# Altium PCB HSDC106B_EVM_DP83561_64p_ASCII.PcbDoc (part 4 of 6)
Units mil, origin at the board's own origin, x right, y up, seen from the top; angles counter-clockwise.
Board outline 8750.24 x 6394.7 mil, 6 copper layers (Top Layer, GND, SIG1, SIG2, GND1, Bottom Layer), stack 60.4 mil thick; 475 components, 330 nets, 1628 pads, 1086 vias.
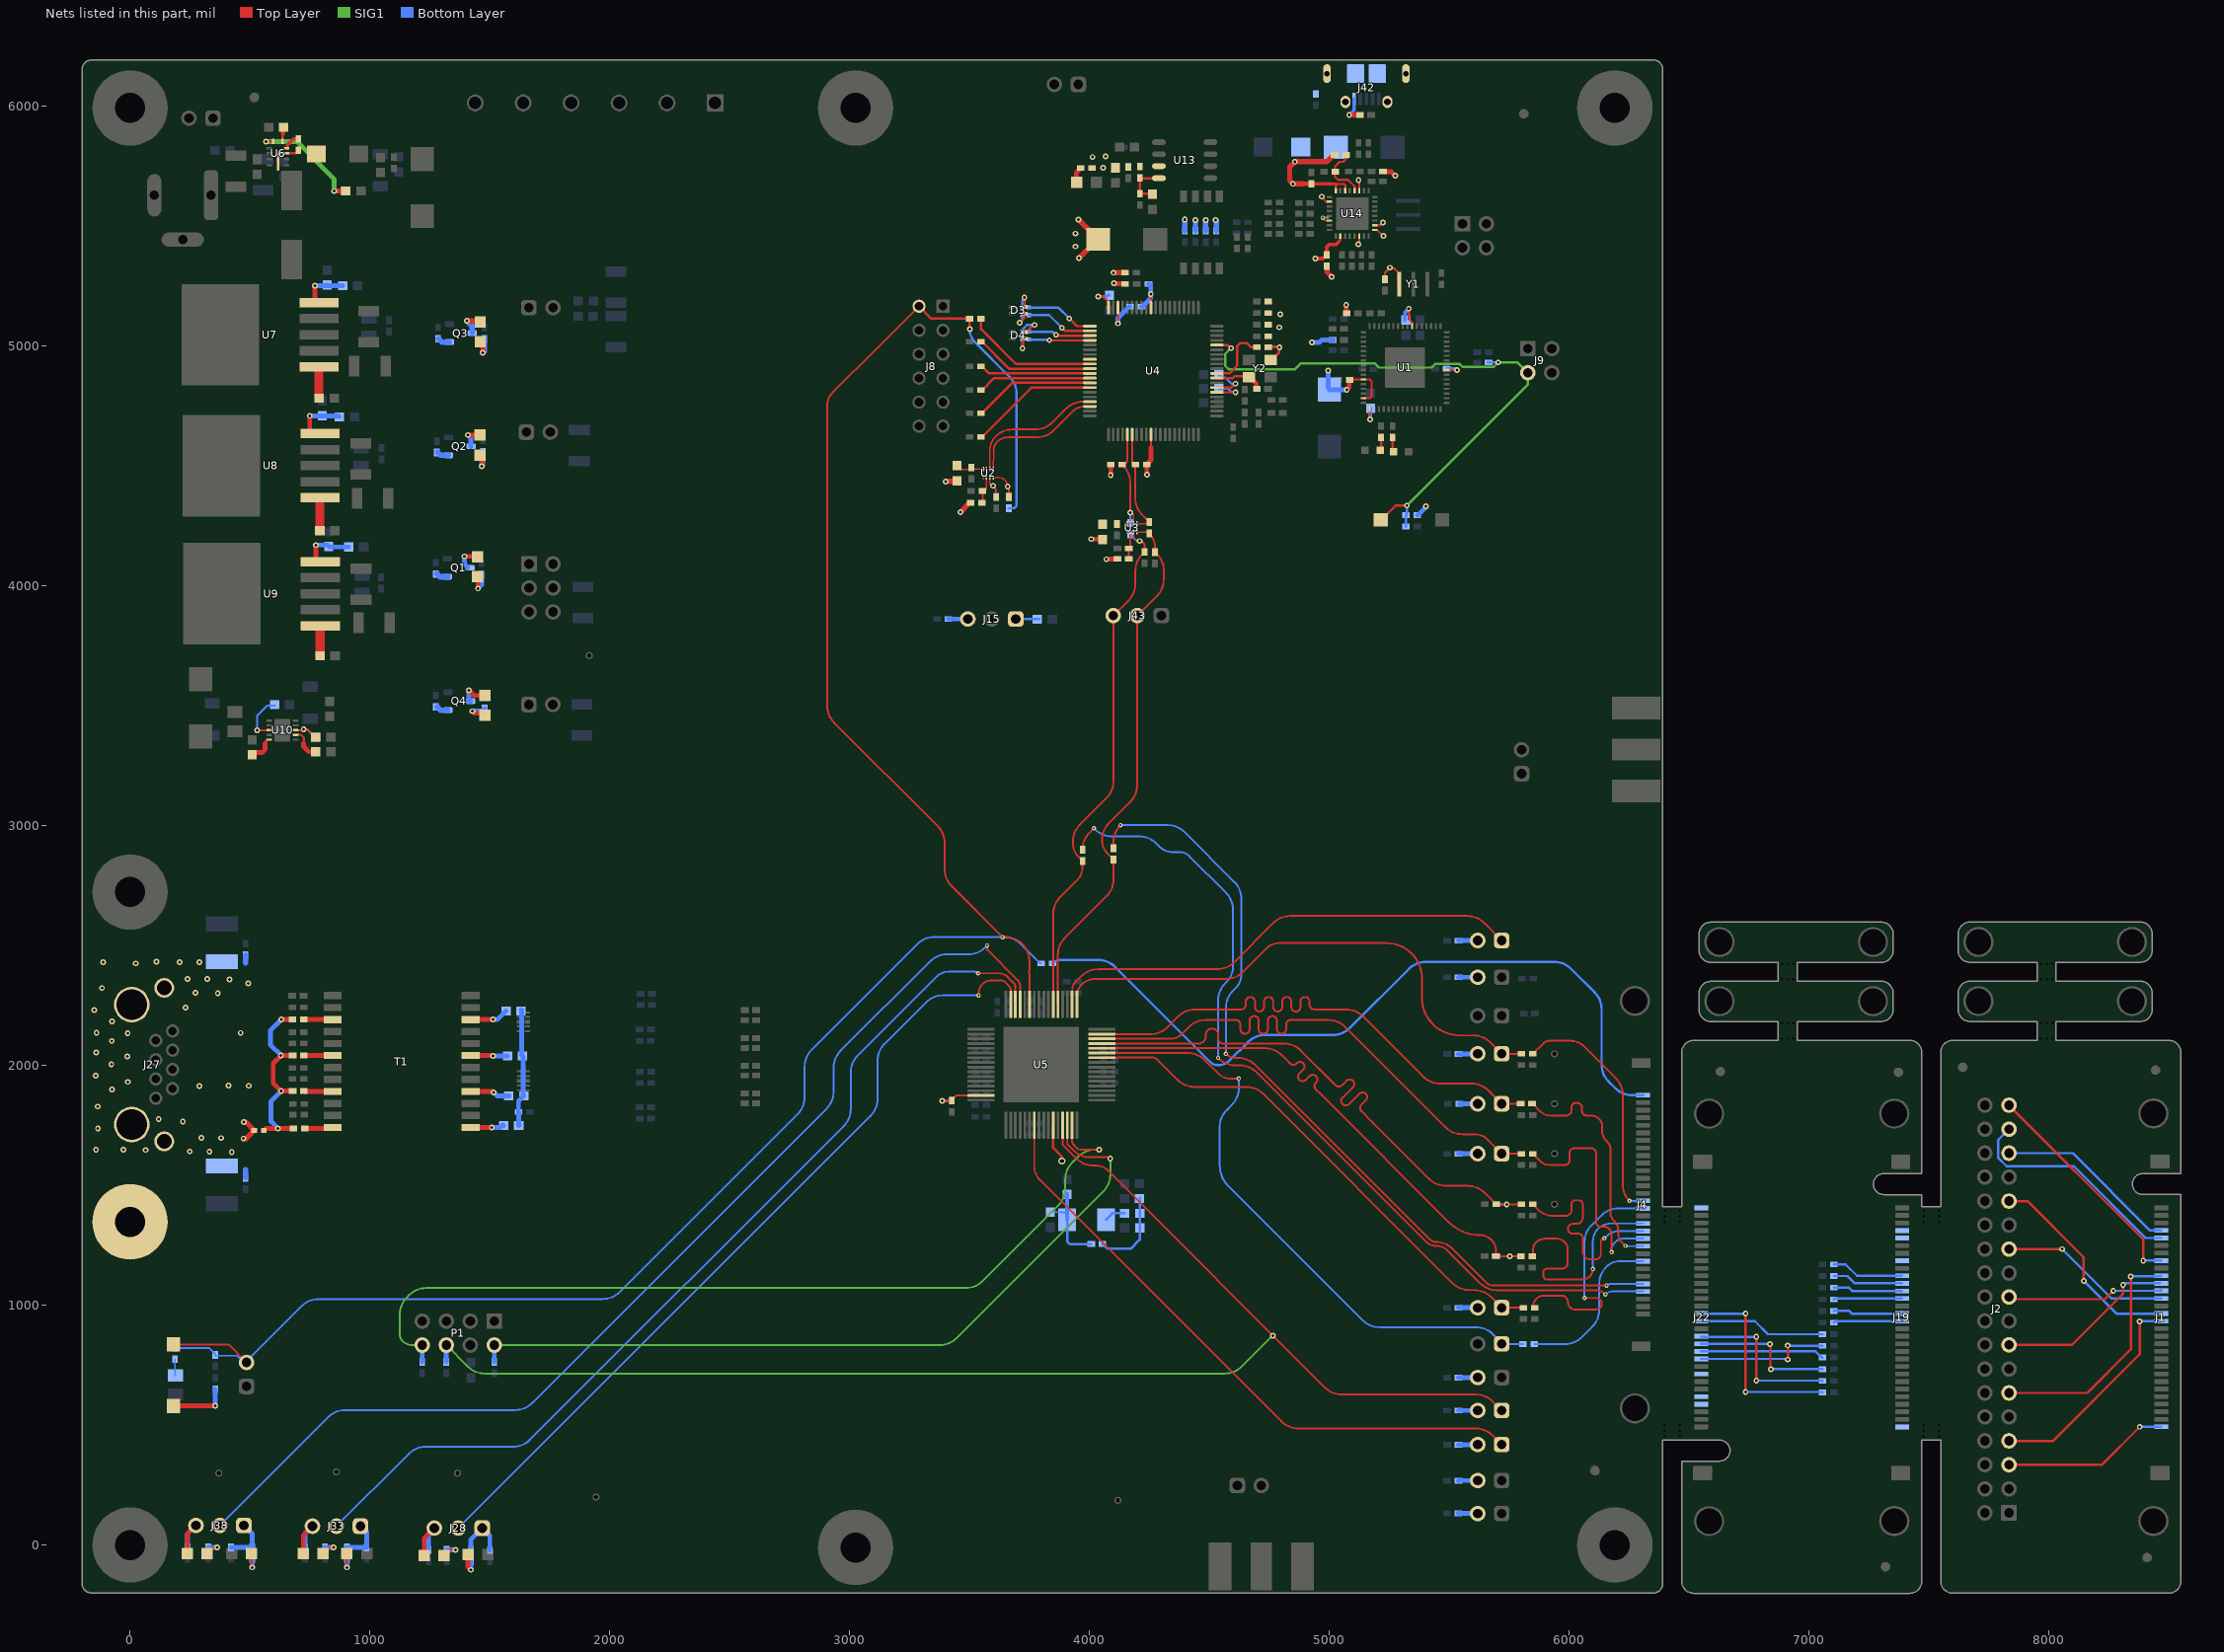
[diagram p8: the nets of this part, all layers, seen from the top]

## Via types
v1: diameter 24, hole 12, Top Layer to Bottom Layer, tented both sides, 905 vias
v2: diameter 24, hole 12, Top Layer to Bottom Layer, 63 vias
v3: diameter 18, hole 7.87, Top Layer to Bottom Layer, tented both sides, 53 vias
v4: diameter 22, hole 10, Top Layer to Bottom Layer, tented both sides, 43 vias
v5: diameter 19.68, hole 7.87, Top Layer to Bottom Layer, 21 vias
v6: diameter 22, hole 12, Top Layer to Bottom Layer, tented both sides, 1 vias

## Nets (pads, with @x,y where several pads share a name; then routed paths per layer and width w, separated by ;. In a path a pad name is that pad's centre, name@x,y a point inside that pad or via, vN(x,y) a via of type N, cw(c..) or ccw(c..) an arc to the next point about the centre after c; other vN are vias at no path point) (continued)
JTAG_TDI: P1.8 R89.2 U5.31 | length 3738.9
  Top Layer w8: U5.31@3927.51,1751.38 3927.51,1685.33 ccw(c3949.83,1685.33) 3934.03,1669.57 3946.87,1656.73 ccw(c3965.96,1675.83) 3965.96,1648.82 v1(4041,1648.82)
  SIG1 w8: P1.8@1218.49,834.31 1178.57,834.31 cw(c1178.57,897.01) 1134.24,852.67 cw(c1157.84,876.27) 1124.47,876.27 1124.47,962.07 cw(c1224.47,962.07) 1153.76,1032.78 1163.6,1042.63 cw(c1234.31,971.92) 1234.31,1071.92 3483.79,1071.92 ccw(c3483.79,1171.92) 3554.5,1101.21 3870.12,1416.82 ccw(c3799.41,1487.53) 3899.41,1487.53 3899.41,1524.82 cw(c3999.41,1524.82) 3928.7,1595.53 3952.7,1619.53 cw(c4023.41,1548.82) 4023.41,1648.82 v1(4041,1648.82)
  Bottom Layer w20: R89.2@1218.49,764.31 P1.8@1218.49,834.31
JTAG_TDO: J34.1 P1.6 R88.2 U5.29 | length 5977
  Top Layer w8: U5.29@3888.14,1751.38 3888.14,1670.56 3947,1611.7 ccw(c4017.71,1682.41) 4017.71,1582.41 4029.6,1582.41 cw(c4029.6,1516.81) 4075.98,1563.2 4982.18,657 ccw(c5052.89,727.71) 5052.89,627.71 5611.43,627.71 cw(c5611.43,527.71) 5682.14,598.42 J34.1@5718.99,561.57
  SIG1 w8: P1.6@1318.49,834.31 1407.9,744.9 ccw(c1478.61,815.61) 1478.61,715.61 4563.94,715.61 ccw(c4563.94,815.61) 4634.65,744.9 4762.57,872.82 v1(4764.47,872.82)
  Bottom Layer w20: R88.2@1318.49,764.31 P1.6@1318.49,834.31
JTAG_TMS: P1.2 R86.2 U5.30 | length 3293.7
  Top Layer w8: U5.30@3907.83,1751.38 3907.83,1673.32 3939.58,1641.57 ccw(c3996.04,1698.04) 3996.04,1618.19 4072.9,1618.19 cw(c4072.9,1598.25) v1(4087,1612.35)
  SIG1 w8: P1.2@1518.49,834.31 3375.72,834.31 ccw(c3375.72,934.31) 3446.43,863.6 4057.71,1474.89 ccw(c3987,1545.6) 4087,1545.6 v1(4087,1612.35)
  Bottom Layer w20: R86.2@1518.49,764.31 P1.2@1518.49,834.31
LED0: J28.2 U5.63 | length 3472
  Top Layer w8: v3(3538,2292.68) 3538,2301.1 cw(c3592.6,2301.1) 3592.6,2355.7 3627.6,2355.7 cw(c3627.6,2325.76) 3648.77,2346.93 3666.31,2329.39 cw(c3653.53,2316.61) 3671.61,2316.61 U5.63@3671.61,2255.08
  Bottom Layer w8: J28.2@1368.5,70.98 3086.87,1789.35 ccw(c3016.16,1860.06) 3116.16,1860.06 3116.16,2019.43 cw(c3216.16,2019.43) 3145.45,2090.15 3318.62,2263.32 cw(c3389.33,2192.61) 3389.33,2292.61 3504.5,2292.61 3504.6,2292.71 v3(3538,2292.68)
LED1: J33.2 U5.62 | length 4006.6
  Top Layer w8: v3(3535.6,2384.61) 3620.76,2384.61 cw(c3620.76,2329.98) 3659.37,2368.63 ; 3659.39,2368.61 3683.45,2344.54 cw(c3664.51,2325.61) 3691.29,2325.61 U5.62@3691.29,2255.08
  Bottom Layer w8: J33.2@860.5,78.98 1162.05,380.53 cw(c1232.76,309.82) 1232.76,409.82 1596.58,409.82 ccw(c1596.58,509.82) 1667.29,439.11 2975.31,1747.13 ccw(c2904.6,1817.84) 3004.6,1817.84 3004.6,1971.13 cw(c3104.6,1971.13) 3033.89,2041.84 3329.6,2337.55 3363.13,2371.08 cw(c3412.38,2321.82) 3412.38,2391.48 3519,2391.48 cw(c3519,2368.01) v3(3535.6,2384.61)
LED2: J38.2 U5.61 | length 4582.9
  Top Layer w8: v3(3573.6,2500.61) 3573.6,2483.1 3700.6,2356.1 cw(c3675.54,2331.05) 3710.98,2331.05 U5.61@3710.98,2255.08
  Bottom Layer w8: J38.2@374.5,81.98 826.54,534.03 cw(c897.26,463.32) 897.26,563.32 1605.83,563.32 ccw(c1605.83,663.32) 1676.54,592.6 2903.59,1819.65 ccw(c2832.88,1890.36) 2932.88,1890.36 2932.88,1989.99 cw(c3032.88,1989.99) 2962.17,2060.7 3335.79,2434.32 cw(c3406.5,2363.61) 3406.5,2463.61 3495.18,2463.61 ccw(c3495.18,2563.61) 3565.89,2492.9 v3(3573.6,2500.61)
MCU_VCC: C10.1 C11.1 C12.1 C21.1 C22.1 C23.1 C112.1 C113.1 C114.1 C129.1 R4.2 R8.2 R36.2 R38.2 R40.2 R41.2 R49.2 R50.2 R52.2 R53.2 R62.2 R63.2 R64.2 R65.2 R66.2 R67.2 R75.1 R76.1 R174.2 R175.2 R178.2 R179.2 R198.2 U1.11 U1.15 U1.40 U4.18 U4.50 U13.3 U14.3 U14.6 U14.8 U14.25 U14.26 | length 2588.9
  Top Layer w9: 5008.25,5676.98 5018.82,5676.98 ; U14.6@5065.88,5647.99 5066.3,5648.41 5066.3,5671.46 5061.03,5676.73 5035.78,5676.73 ; C11.1@5091.15,4861.48 5168.22,4861.48 5176,4853.7 5176,4789.7 5169.04,4782.74 U1.15@5142.77,4782.74 ; U14.3@5124.94,5647.99 v1@5124.94,5690.64 ; U14.25@5189.32,5484.41 5199.52,5484.41 5224.41,5459.52 v1(5226.43,5459.52) ; U14.26@5189.9,5504.29 5212.89,5504.29 v1(5223.77,5515.18) ; U1.40@5489.22,4900.85 v1(5532.85,4900.85) ; 5018.82,5676.98 5029.39,5676.98 5029.64,5676.73 5035.78,5676.73 ; 5018.82,5676.98 5026.51,5669.29 U14.8@5026.51,5647.99 5026.93,5648.41 5026.93,5668.3 5027.14,5668.1 5035.78,5676.73
  Top Layer w10: v1(4118.83,5094.61) U4.18@4118.83,5161.23 ; 4256.63,4577.61 U4.50@4256.63,4631.7
  Top Layer w15: C129.1@4925.63,5676.98 5008.25,5676.98
  Top Layer w20: v1(4007.6,4195.61) 4054.1,4195.61 R41.2@4055.6,4194.11 ; v1(4070.38,4111.55) 4101.5,4111.55 4101.75,4111.8 4115.17,4111.8 R38.2@4116.98,4113.61 ; v1(4088.6,4462.61) R66.2@4088.6,4506.61 ; v1(4239.6,4463.61) 4239.1,4464.11 4239.1,4506.61 4242.54,4506.61 4244.35,4508.42 4244.35,4511.85 4256.63,4524.14 4256.63,4577.61 ; 4891.01,5676.98 C129.1@4925.63,5676.98 ; R179.2@4989,5334.08 4990.81,5332.27 4990.81,5308.3 v1(5009.12,5289.99) ; R8.2@5070.41,5138.14 v1(5070.41,5172.52) ; v1(5072.8,4817.7) 5072.8,4818.78 5083.11,4829.08 5083.11,4858.58 C11.1@5084.22,4859.7 ; R178.2@5223.62,5729 5225.43,5727.19 5258.15,5727.19 5273.72,5711.62 5273.72,5711.18 v1(5275.24,5711.18)
  Top Layer w22: v1(3400.32,4435.84) 3400.7,4436.22 3445.71,4436.22 R40.2@3448.6,4439.11 ; v1(3461.6,4307.61) 3461.98,4307.99 3461.98,4308.55 3500.04,4346.61 R36.2@3503.98,4346.61 ; v1(3953.6,5527.76) 3954.35,5527.76 3997.31,5484.8 3997.31,5482.83 C21.1@4034.54,5445.61 ; v1(3956.6,5367.67) C21.1@4034.54,5445.61 ; C21.1@4036.5,5445.61 C21.1@4034.54,5445.61 ; v1(4100.6,5306.61) C22.1@4148.17,5306.61 ; v1(4102.3,5262.61) 4102.84,5262.61 4105.03,5260.42 4147.35,5260.42 C23.1@4148.17,5259.61 ; 4891.01,5676.98 v1(4848.25,5676.98) 4834.63,5690.61 4834.63,5747.61 v1(4856.63,5769.61) 4989.63,5769.61 5017.63,5797.61 R198.2@5022.63,5797.61
  Bottom Layer w15: C12.1@5489.62,4905.7 5528,4905.7 v1(5532.85,4900.85)
  Bottom Layer w20: v1(4118.83,5094.61) 4118.83,5118.28 4165.29,5164.73 R76.1@4169.23,5164.73 ; v1(4927,5015.7) 4958,5015.7 4968,5025.7 R4.2@5019,5025.7 ; v1(4995.6,4898.08) 4995.6,4831.77 ccw(c5012.67,4831.77) C10.1@5000.6,4819.7 ; C10.1@5000,4820.79 5003.09,4817.7 v1(5072.8,4817.7) ; R75.1@5366.62,4295.61 5370.56,4295.61 5402.25,4327.3 5402.25,4331.23 v1(5403.02,4332)
  Bottom Layer w22: R62.2@4397.6,5482.23 v1(4397.6,5528.61) ; R63.2@4441.6,5482.23 v1(4441.6,5526.61) ; R64.2@4484.6,5482.23 v1(4484.6,5526.61) ; v1(4525.6,5526.61) 4528.6,5523.61 R65.2@4528.6,5482.23 ; v1(4484.6,5526.61) ccw(c4483.6,5526.61) 4483.6,5527.61 v1(4484.6,5526.61)
  other v1: 4791.66,5078.25 4795.6,5133.5 3941.6,5415.61 3941.6,5469.61 5122,5692.7 4057.6,5744.1 4012.6,5788.61 4066.6,5791.61
MDC: J43.3 R11.1 R48.1 R54.1 U3.3 U5.54 | length 2210.2
  Top Layer w6: U3.3@4183.49,4224.89 4183.49,4213.72 ccw(c4209.6,4213.72) v1(4209.6,4187.61)
  Top Layer w8: U5.54@3848.77,2255.08 3848.77,2632.36 cw(c3948.77,2632.36) 3878.06,2703.07 3949.53,2774.54 ccw(c3896.75,2827.31) 3971.39,2827.31 R11.1@3971.39,2852.9 3954.58,2869.71 cw(c4012.47,2927.61) 3930.6,2927.61 3930.6,2933.18 cw(c4030.6,2933.18) 3959.89,3003.9 4070.31,3114.32 ccw(c3999.6,3185.03) 4099.6,3185.03 J43.3@4099.6,3876.61 4162.31,3939.32 ccw(c4091.6,4010.03) 4191.6,4010.03 4191.6,4064.61 cw(c4284.84,4064.61) 4218.91,4130.54 R48.1@4230.1,4141.73 4230.1,4167.11 ccw(c4209.6,4167.11) v1(4209.6,4187.61)
  Bottom Layer w8: R54.1@4169.71,4215.05 4188.35,4196.41 ccw(c4209.6,4217.66) v1(4209.6,4187.61)
MDC_1: J1.8 J2.31 | length 769.1
  Bottom Layer w10: J2.31@7833.6,1634.61 8099.99,1634.61 8422.39,1312.2 J1.8@8469.11,1312.2
MDC_2: J22.8
MDC_CS: J4.8 R11.2 | length 3629.3
  Top Layer w8: R11.2@3971.39,2900.15 3971.39,2900.97 cw(c4071.39,2900.97) 4000.68,2971.69 v3(4018.6,2989.61) ; v3(4536.62,2031.61) 4537.8,2030.42 ccw(c4608.51,2101.13) 4540.24,2028.07 ccw(c4608.51,2101.13) 4608.51,2001.13 4626.65,2001.13 cw(c4626.65,1901.13) 4697.36,1971.84 5404.34,1264.86 ccw(c5446,1306.52) 5446,1247.61 cw(c5446,1180.98) 5493.11,1228.09 5628.93,1092.27 ccw(c5699.64,1162.98) 5699.64,1062.98 6109.64,1062.98 cw(c6109.64,1003.65) v3(6151.6,1045.61)
  Bottom Layer w8: v3(4018.6,2989.61) 4022.78,2985.43 ccw(c4093.49,3056.14) 4093.49,2956.14 4206.64,2956.14 cw(c4206.64,2856.14) 4277.35,2926.85 4289.6,2914.61 ccw(c4349.95,2974.96) 4349.95,2889.61 4377.32,2889.61 cw(c4377.32,2833.4) 4417.06,2873.14 4568.6,2721.61 cw(c4497.89,2650.9) 4597.89,2650.9 4597.89,2410.8 cw(c4511.35,2410.8) 4572.54,2349.61 4565.91,2342.97 ccw(c4636.62,2272.26) 4536.62,2272.26 v3(4536.62,2031.61) ; v3(6151.6,1045.61) cw(c6181.03,1016.18) 6181.03,1057.8 J4.8@6308.86,1057.8
MDC_LP: J19.8
MDC_MSP: R54.2 R66.1 U3.6 U4.45 | length 445
  Top Layer w6: v1(4169.71,4305.61) cw(c4169.71,4291.83) 4183.49,4291.83 U3.6@4183.49,4260.32
  Top Layer w8: U4.45@4158.2,4631.7 4158.2,4528.97 cw(c4135.84,4528.97) R66.1@4135.84,4506.61 4140.42,4502.03 cw(c4069.71,4431.32) 4169.71,4431.32 v1(4169.71,4305.61)
  Bottom Layer w8: R54.2@4169.71,4262.29 v1(4169.71,4305.61)
MDIO: J43.2 R12.1 R56.1 R85.2 U3.4 U5.53 | length 2234.9
  Top Layer w6: U3.4@4197.27,4224.89 4244.07,4224.89 cw(c4244.07,4219.36) R56.1@4249.6,4219.36
  Top Layer w8: U5.53@3868.46,2255.08 3868.46,2461.73 cw(c3968.46,2461.73) 3897.75,2532.45 4071.22,2705.92 ccw(c4000.51,2776.63) 4100.51,2776.63 R12.1@4100.51,2858.98 4075.02,2884.47 cw(c4129.16,2938.61) 4052.6,2938.61 4052.6,2941.18 cw(c4152.6,2941.18) 4081.89,3011.9 4170.31,3100.32 ccw(c4099.6,3171.03) 4199.6,3171.03 J43.2@4199.6,3876.61 4280.31,3957.32 ccw(c4209.6,4028.03) 4309.6,4028.03 4309.6,4067.61 ccw(c4219.98,4067.61) 4283.35,4130.98 R85.2@4273.1,4141.23 4273.1,4162.63 ccw(c4192.86,4162.63) R56.1@4249.62,4219.34
MDIO_1: J1.10 J2.33 | length 957.2
  Bottom Layer w10: J2.33@7833.6,1734.61 7788.24,1689.25 7788.24,1615.82 7824.1,1579.96 7833.27,1579.96 7833.42,1579.96 cw(c7833.6,1534.61) 7833.78,1579.96 7833.93,1579.96 8104.04,1579.96 8403.29,1280.71 J1.10@8469.11,1280.71
MDIO_2: J22.10
MDIO_CS: J4.10 R12.2 | length 3550.9
  Top Layer w8: R12.2@4100.51,2900.15 4100.51,2932.48 cw(c4199.68,2932.48) v3(4129.55,3002.61) ; v3(4568.6,2048.94) ccw(c4611.33,2091.67) 4611.33,2031.24 4628.75,2031.24 cw(c4620.18,1931.61) 4690.89,2002.32 5417.48,1275.73 ccw(c5444.6,1302.84) 5444.6,1264.49 cw(c5444.6,1167.2) 5513.4,1236 5656.6,1092.79 ccw(c5682.02,1118.22) 5682.02,1082.26 v3(6156.02,1082.26)
  Bottom Layer w8: v3(4129.55,3002.61) 4326.04,3002.61 cw(c4326.04,2902.61) 4396.75,2973.32 4604.31,2765.76 cw(c4533.6,2695.05) 4633.6,2695.05 4633.6,2380.48 cw(c4551.66,2380.48) 4609.6,2322.54 4597.89,2310.83 ccw(c4668.6,2240.12) 4568.6,2240.12 v3(4568.6,2048.94) ; v3(6156.02,1082.26) cw(c6172.99,1065.29) 6172.99,1089.29 J4.10@6308.86,1089.29
MDIO_LP: J19.10
MDIO_MSP: R56.2 R67.1 U3.5 U4.46 | length 446.6
  Top Layer w6: U3.5@4197.27,4260.32 4234.43,4260.32 ccw(c4234.43,4281.78) R56.2@4249.6,4266.61
  Top Layer w8: U4.46@4177.89,4631.7 4177.89,4520.07 ccw(c4191.35,4520.07) R67.1@4191.35,4506.61 4191.35,4382.61 4191.35,4366.27 ccw(c4291.35,4366.27) 4191.35,4366.22 ccw(c4291.35,4366.27) 4214.29,4302.54 ccw(c4291.35,4366.27) 4220.64,4295.56 R56.2@4249.6,4266.61
MSP_XIN: C15.1 U4.69 Y2.3 | length 203.6
  Top Layer w10: U4.69@4531.24,4866.94 4597.38,4866.94 4605.93,4875.48 4661.02,4875.48 Y2.3@4665.32,4871.17 Y2.3@4669.26,4871.17 ; C15.1@4696.17,4823.79 C15.1@4697.35,4822.61
  Top Layer w20: Y2.3@4669.26,4871.17 4696.17,4844.26 C15.1@4696.17,4823.79
MSP_XOUT: R68.2 U4.70 | length 272.3
  Top Layer w10: U4.70@4531.24,4886.62 4583.06,4886.62 4615.6,4919.16 4615.6,4999.61 4627.65,5011.66 4657.72,5011.66 4673.78,4995.61 R68.2@4697.98,4995.61
NetC4_1: C4.1 R7.2 Y1.1 | length 207.6
  Top Layer w9: C4.1@5232.1,5279.17 5232.2,5279.27 5232.2,5307.2 v1(5252.6,5327.61) 5254.25,5325.95 5269.01,5325.95 5288.17,5306.79 5288.17,5261.98 Y1.1@5291.54,5258.61
  Bottom Layer w9: R7.2@5232.1,5279.17 5232.1,5307.11 v1(5252.6,5327.61)
NetC6_1: C6.1 U1.55 | length 133.3
  Top Layer w9: v1(5331.6,5156.61) 5331.6,5113.09 5345.52,5099.17 U1.55@5345.52,5083.92
  Bottom Layer w15: C6.1@5315.99,5108.2 5315.99,5141 v1(5331.6,5156.61)
NetC7_1: C7.1 U1.17 | length 91
  Top Layer w9: U1.17@5168.32,4737.47 5168.32,4696.38 v1(5170,4694.7)
  Bottom Layer w15: v1(5170,4694.7) 5171,4694.7 C7.1@5171,4741.2
NetC13_1: C13.1 R40.1 U2.7 U2.8 | length 134.6
  Top Layer w6: R40.1@3448.6,4502.1 3464.25,4486.45 3499.42,4486.45 C13.1@3507.2,4494.23 3513.2,4488.23 U2.8@3557.26,4488.23 U2.7@3571.04,4488.23
NetC14_1: C14.1 R41.1 U3.7 U3.8 | length 13.8
  Top Layer w6: U3.8@4155.93,4260.32 U3.7@4169.71,4260.32
NetC16_1: C16.1 R68.1 Y2.1 | length 160.2
  Top Layer w10: R68.1@4745.22,4995.61 4787.1,4995.61 4789.78,4992.93 4789.78,4972.01 4759.81,4942.04 Y2.1@4755.87,4942.04
  Bottom Layer w10: C16.1@4745.22,4995.61 v1(4792.46,4995.61)
NetC17_1: C17.1 U4.67 | length 170.7
  Top Layer w10: U4.67@4531.24,4827.57 4531.58,4827.91 4592.06,4827.91 4607.84,4843.7 v1(4609.32,4843.7)
  Bottom Layer w10: C17.1@4539.09,4881.61 4551.37,4869.34 4566.42,4869.34 4592.06,4843.7 v1(4609.32,4843.7)
NetC18_1: C18.1 U4.20 | length 128
  Top Layer w10: v1(4036.6,5207.61) 4056.91,5207.61 4078.56,5185.95 4078.56,5185.26 4079.46,5184.36 U4.20@4079.46,5161.23
  Bottom Layer w10: v1(4036.6,5207.61) 4071.6,5207.61 4079.6,5215.61 C18.1@4083.6,5211.61
NetC20_1: C20.1 U4.66 | length 155
  Top Layer w10: U4.66@4531.24,4807.88 v1(4609.32,4807.88)
  Bottom Layer w10: C20.1@4538.76,4823.24 4577.34,4823.24 4591.92,4808.66 4608.54,4808.66 v1(4609.32,4807.88)
NetC24_1: C24.1 R76.2 U4.11 | length 175
  Top Layer w10: v1(4255.83,5216.63) 4256.61,5215.85 U4.11@4256.63,5161.23
  Bottom Layer w20: R76.2@4216.47,5164.73 4220.41,5164.73 4255.83,5200.16 v1(4255.83,5216.63) 4255.83,5253.69 4249.92,5259.61 C24.1@4246.62,5259.61
NetC47_1: C47.1 R80.1 | length 68.2
  Bottom Layer w8: R80.1@187.29,775.18 187.29,709.8 C47.1@189.29,707.8
NetC48_1: C48.1 R77.1 R81.1 XTAL1.2 | length 383
  Bottom Layer w8: C48.1@3835.97,1388.79 3882.12,1388.79 cw(c3882.12,1353.65) XTAL1.2@3906.97,1378.5
  Bottom Layer w10: XTAL1.2@3907.26,1356.8 3907.26,1265.51 3916.97,1255.8 R81.1@4007.35,1255.8
  Bottom Layer w15: XTAL1.2@3903.96,1388.79 XTAL1.2@3906.97,1391.8 ; R77.1@3906.97,1466.31 XTAL1.2@3906.97,1391.8 ; XTAL1.2@3907.26,1356.8 3906.97,1357.09 3906.97,1378.5 XTAL1.2@3906.97,1391.8
NetC49_1: C49.1 R78.1 R81.2 R82.1 | length 353.6
  Bottom Layer w10: R81.2@4054.59,1255.8 4074.59,1235.8 4171.97,1235.8 4209.97,1273.8 C49.1@4209.97,1322.8 R78.1@4209.97,1383.8 4209.97,1447.3 R82.1@4209.47,1447.8
NetC51_2: C51.2 R83.1 U5.15 | length 214.4
  Top Layer w8: v1(3385.57,1853.23) C51.2@3426.41,1853.23 3426.41,1857.17 3444.52,1875.27 U5.15@3547.71,1875.27
  Bottom Layer w8: v1(3385.57,1853.23) R83.1@3426.41,1853.23
NetC54_1: C54.1 C69.1 C72.1 C79.1 R126.2 | length 504.7
  Bottom Layer w20: C54.1@1623.1,1751.61 C54.1@1620.5,1749 1619.94,1749.56 1619.94,1805.44 R126.2@1619.38,1806 1619.38,1851.92 1640.98,1873.53 C69.1@1641.97,1873.53 1639.23,1876.27 1639.23,2037.26 C72.1@1636.5,2040 1633.23,2043.26 C79.1@1633.23,2231.41 ; C79.1@1629.97,2231.68 C79.1@1633.23,2228.41
NetC54_2: C54.2 T1.1 | length 144
  Top Layer w20: T1.1@1419.86,1741.7 T1.1@1419.86,1741.7 1508.05,1741.65 v1(1508.09,1741.61)
  Bottom Layer w20: v1(1508.09,1741.61) 1542.38,1741.61 1553.64,1752.87 C54.2@1557.5,1749
NetC56_1: C56.1 U6.4 | length 73.4
  Top Layer w10: U6.4@652.03,5825.18 655.72,5825.18 655.8,5825.26 655.8,5838.31
  Top Layer w15: 655.8,5838.31 681.68,5864.19 C56.1@701.6,5864.19
NetC56_2: C56.2 L1.1 U6.3 U6.12 | length 125.8
  Top Layer w10: U6.12@616.6,5767.58 616.6,5798.43 623.67,5805.5 U6.3@652.03,5805.5 694.08,5805.5 701.6,5813.01 C56.2@701.6,5816.95
NetC62_1: C62.1 U6.5 | length 61
  Top Layer w10: U6.5@636.28,5853.72 636.28,5886.66
  Top Layer w20: 637.88,5886.66 637.88,5910.89 C62.1@640.6,5913.61
NetC69_2: C69.2 T1.4 | length 166.7
  Top Layer w20: T1.4@1419.86,1891.7 1511.01,1891.7 1514.57,1888.14 v1(1515.65,1888.14)
  Bottom Layer w20: v1(1515.65,1888.14) 1530.31,1873.48 1578.93,1873.48 C69.2@1578.98,1873.53
NetC72_2: C72.2 T1.7 | length 214.2
  Top Layer w20: T1.7@1419.86,2041.7 1510.88,2041.7 1512.58,2040 v1(1513.66,2040) ; T1.7@1424.59,2041.61 1484.43,2041.61
  Bottom Layer w20: v1(1513.66,2040) C72.2@1573.5,2040
NetC79_2: C79.2 T1.10 | length 162.7
  Top Layer w20: T1.10@1419.86,2191.7 v1(1513.87,2191.7)
  Bottom Layer w20: v1(1513.87,2191.7) 1531.2,2191.7 C79.2@1567.5,2228
NetC82_1: C82.1 R107.1 R114.1 R117.1 R123.1 | length 819.7
  Top Layer w20: C82.1@557.28,1729.61 558.94,1729.61 566.94,1737.61 v1(616,1737.61) R107.1@680.98,1737.61 ; v1@628,2191 cw(c630.64,2188.36) v1(630.64,2192.09) R123.1@676.38,2192.09 ; R114.1@677.76,1893.61 v1(629.82,1893.61) 597,1926.43 597,2009.08 629.47,2041.56 v1(629.47,2042.64) R117.1@677.76,2041.7
  Bottom Layer w20: v1(616,1737.61) 616,1738.69 587.95,1766.74 587.95,1851.73 v1(629.82,1893.61) ; v1(629.47,2042.64) 585,2087.12 585,2146.45 v1(630.64,2192.09)
NetC94_1: C94.1 U10.7 | length 135.4
  Top Layer w9: U10.7@690.12,3378.7 U10.7@690.12,3379.01 712.68,3379.01 724,3367.7 724,3342.7
  Top Layer w20: 724,3342.7 724,3330.22 745.62,3308.61 C94.1@774.1,3308.61
NetC115_1: C115.1 R174.1 R176.2 U13.4 | length 199.7
  Top Layer w10: C115.1@4263.6,5633.61 4260.65,5636.56 R176.2@4210,5636.56 R174.1@4210,5701.42 4210.72,5700.7 U13.4@4289.72,5700.7
NetC116_1: C116.1 C117.2 D9.2 J42.1 | length 120.9
  Top Layer w20: v1(5082.98,5963.68) 5083.8,5964.5 5121.67,5964.5 C117.2@5127.42,5964.5
  Bottom Layer w15: v1(5082.98,5963.68) 5103.65,5984.35 5103.65,6029.3 J42.1@5103.65,6031.3
NetC126_1: C126.1 R198.1 U14.4 | length 234.5
  Top Layer w9: R198.1@5069.24,5797.7 5067.18,5795.64 5067.18,5778.65 5057.23,5768.7 5043,5768.7 5024.62,5750.32 C126.1@5024.62,5727.7 5024.62,5705.08 5036,5693.7 5078,5693.7 5105.25,5666.45 U14.4@5105.25,5647.99
NetD1_2: D1.2 R1.1 | length 54.9
  Top Layer w10: D1.2@5211.78,4565.7 ccw(c5201.59,4575.89) 5216,4575.89 R1.1@5216,4619.46
NetD2_2: D2.2 R2.1 | length 60.4
  Top Layer w10: R2.1@5264,4619.46 5264,4568.73 ccw(c5276.29,4568.73) D2.2@5267.6,4560.04
NetD3_1: D3.1 R70.1 | length 85.2
  Top Layer w10: v1(3708.6,5097.61) 3728.72,5117.73 D3.1@3728.72,5136.23
  Bottom Layer w10: v1(3708.6,5097.61) 3721.06,5110.06 R70.1@3721.06,5129.86 R70.1@3720.27,5129.86
NetD3_2: D3.2 R69.1 | length 84.2
  Top Layer w10: D3.2@3728.72,5163.79 v1(3728.72,5202.61)
  Bottom Layer w10: R69.1@3721.86,5162.38 R69.1@3721.06,5161.57 3721.06,5191.15 3728.72,5198.82 v1(3728.72,5202.61)
NetD4_1: D4.1 R72.1 | length 83.5
  Top Layer w10: v1(3720.6,4990.61) 3723.28,4993.28 3723.28,5028.2 3726.15,5031.08 D4.1@3730.17,5031.08
  Bottom Layer w10: v1(3720.6,4990.61) 3720.85,4990.86 3720.85,5026.89 R72.1@3721.11,5027.14
NetD4_2: D4.2 R71.1 | length 120
  Top Layer w10: D4.2@3730.17,5058.64 3736.07,5058.64 3763.36,5085.93 3767.92,5085.93 v1(3770.6,5088.61)
  Bottom Layer w10: R71.1@3721.11,5060.61 3721.9,5060.61 3725.17,5063.87 3725.17,5074.21 3739.57,5088.61 v1(3770.6,5088.61)
NetD5_1: D5.1 R102.1 | length 119.6
  Top Layer w20: D5.1@1448.6,4039.27 1450.6,4037.27 v1(1450.6,3989.61)
  Bottom Layer w20: v1(1450.6,3989.61) 1465.6,4004.61 R102.1@1465.6,4052.47
NetD5_2: D5.2 Q1.3 | length 110.1
  Top Layer w20: v1(1394.6,4123.61) 1448.6,4123.61 D5.2@1450.6,4125.61
  Bottom Layer w20: v1(1394.6,4123.61) 1394.6,4090.47 1407.56,4077.51 Q1.3@1407.56,4075.7
NetD6_1: D6.1 R103.1 | length 109.5
  Top Layer w20: D6.1@1458,4546.36 1466.6,4537.76 v1(1466.6,4499.61)
  Bottom Layer w20: v1@1469.6,4501.61 1471.6,4503.61 R103.1@1471.6,4559.98
NetD6_2: D6.2 Q2.3 | length 102.4
  Top Layer w20: v1@1409,4627.7 1410.34,4629.04 D6.2@1458,4629.04
  Bottom Layer w20: v1@1409,4629.7 1409,4628.55 1421.41,4616.14 1421.41,4583.91 1421.65,4583.68 Q2.3@1421.65,4582.1
  other v1: 1408,4629.7
NetD7_1: D7.1 R104.1 | length 110.4
  Top Layer w23: D7.1@1460,5018.36 1470.6,5007.76 v1(1470.6,4972.61)
  Bottom Layer w23: v1(1470.6,4972.61) 1477.6,4979.61 R104.1@1477.6,5029.98
NetD7_2: D7.2 Q3.3 | length 117.5
  Top Layer w23: v1(1405,5105.7) 1455.34,5105.7 D7.2@1460,5101.04
  Bottom Layer w23: v1@1404.54,5105.7 1404.73,5105.7 1405.19,5105.24 1405.19,5104.51 1425.21,5084.49 1425.21,5055.01 1425.52,5054.7 Q3.3@1426.24,5054.7
NetD8_1: D8.1 R105.1 | length 118.9
  Top Layer w20: v1(1426.4,3477.58) 1427.48,3477.58 1435.89,3469.17 1469.89,3469.17 D8.1@1478.6,3460.46
  Bottom Layer w20: v1(1426.4,3477.58) 1427.17,3478.34 1466.96,3478.34 1472.85,3484.24 1476.79,3484.24 1478.6,3486.05 R105.1@1478.6,3489.98
NetD8_2: D8.2 Q4.3 | length 126.7
  Top Layer w20: v1(1412.6,3564.8) 1434.26,3543.13 D8.2@1478.6,3543.13
  Bottom Layer w20: v1(1412.6,3564.8) 1412.6,3521.51 1414.41,3519.7 Q4.3@1420.24,3519.7
NetJ15_1: J15.1 R90.2 | length 95.6
  Bottom Layer w10: J15.1@3697.83,3867 3702.83,3862 R90.2@3791.33,3862
NetJ15_3: J15.3 R87.1 | length 88.4
  Bottom Layer w20: R87.1@3411.45,3862 J15.3@3492.83,3862 J15.3@3497.83,3867
NetJ28_1: J28.1 R149.2 R150.2 | length 215.6
  Bottom Layer w20: R149.2@1421.5,-19.77 1421.5,23.98 J28.1@1468.5,70.98 1500,39.48 R150.2@1500,-21.38
NetJ28_3: J28.3 LD1.2 R148.1 | length 233
  Top Layer w20: LD1.2@1226.66,-44 1226.66,29.14 J28.3@1268.5,70.98
  Bottom Layer w20: R148.1@1244.5,-19.77 1244.5,46.98 J28.3@1268.5,70.98
NetJ29_2: J29.2 R151.1 | length 80.8
  Bottom Layer w20: R151.1@5538.56,1631.93 5538.56,1632.34 J29.2@5618.99,1632.34
NetJ30_2: J30.2 R153.1 | length 80.8
  Bottom Layer w20: R153.1@5542.27,1840.17 5542.27,1840.58 J30.2@5618.99,1840.58 J30.2@5622.7,1840.58
NetJ31_2: J31.2 R156.1 | length 80.8
  Bottom Layer w20: R156.1@5538.56,2048.41 5538.56,2048.82 J31.2@5618.99,2048.82
NetJ32_2: J32.2 R160.1 | length 80.8
  Bottom Layer w20: R160.1@5538.56,989.59 5538.56,990 J32.2@5618.99,990
NetJ33_1: J33.1 R161.2 R162.2 | length 181.3
  Bottom Layer w20: R161.2@904,-9.77 R162.2@986,-9.77 986,53.48 J33.1@960.5,78.98
NetJ33_3: J33.3 LD3.2 R159.1 | length 231.2
  Top Layer w20: LD3.2@722.56,-34.95 722.56,41.04 J33.3@760.5,78.98
  Bottom Layer w20: R159.1@729.5,-9.77 729.5,47.98 J33.3@760.5,78.98
NetJ34_2: J34.2 R163.1 | length 80.8
  Bottom Layer w20: R163.1@5538.56,561.16 5538.56,561.57 J34.2@5618.99,561.57
NetJ35_2: J35.2 R164.1 | length 82.2
  Bottom Layer w20: R164.1@5537.22,132.61 5537.69,132.14 5618.53,132.14 J35.2@5618.99,131.67
NetJ36_2: J36.2 R165.1 | length 80.8
  Bottom Layer w20: R165.1@5538.56,268.61 5538.56,269.01 J36.2@5618.99,269.01
NetJ37_2: J37.2 R167.1 | length 80.8
  Bottom Layer w20: R167.1@5538.56,418.62 5538.56,419.03 J37.2@5618.99,419.03
NetJ38_1: J38.1 R170.2 R171.2 | length 195.3
  Bottom Layer w20: R171.2@420.5,-9.77 R170.2@509.5,-9.77 509.5,46.98 J38.1@474.5,81.98
NetJ38_3: J38.3 LD5.2 R168.1 | length 238.1
  Top Layer w20: LD5.2@238.66,-35 238.66,46.14 J38.3@274.5,81.98
  Bottom Layer w20: R168.1@239.5,-9.77 239.5,46.98 J38.3@274.5,81.98
NetJ39_2: J39.2 R169.1 | length 80.8
  Bottom Layer w20: R169.1@5538.56,698.36 5538.56,698.77 J39.2@5618.99,698.77
NetJ40_2: J40.2 R172.1 | length 80.8
  Bottom Layer w20: R172.1@5538.56,2521 5538.56,2521.41 J40.2@5618.99,2521.41
NetJ41_2: J41.2 R173.1 | length 80.8
  Bottom Layer w20: R173.1@5538.56,2367.87 5538.56,2368.28 J41.2@5618.99,2368.28
NetJ42_6: J42.6 J42.7 J42.8 J42.9 J42.10 J42.11 R177.1
NetLD1_1: LD1.1 R147.2 | length 93.7
  Top Layer w10: LD1.1@1309.34,-44 1333.56,-19.77 v1(1356.73,-19.77)
  Bottom Layer w20: R147.2@1320.5,-19.77 v1(1356.73,-19.77)
NetLD2_1: LD2.1 R149.1 | length 104.8
  Top Layer w20: LD2.1@1408.66,-40 1408.66,-90.41 v1(1421.5,-103.25)
  Bottom Layer w20: v1(1421.5,-103.25) R149.1@1421.5,-67.02
NetLD3_1: LD3.1 R157.2 | length 90.2
  Top Layer w10: LD3.1@805.23,-34.95 830.41,-9.77 v1(848.73,-9.77)
  Bottom Layer w20: R157.2@812.5,-9.77 v1(848.73,-9.77)
NetLD4_1: LD4.1 R161.1 | length 94.5
  Top Layer w10: v1(904,-93.25) 904.16,-93.09 LD4.1@904.16,-35
  Bottom Layer w20: v1(904,-93.25) R161.1@904,-57.02
NetLD5_1: LD5.1 R166.2 | length 88
  Top Layer w10: LD5.1@321.34,-35 346.53,-9.8 v1(362.72,-9.8)
  Bottom Layer w20: R166.2@326.49,-9.8 v1(362.72,-9.8)
NetLD6_1: LD6.1 R170.1 | length 95.8
  Top Layer w10: LD6.1@506.34,-35 506.34,-90.09 v1(509.5,-93.25)
  Bottom Layer w20: v1(509.5,-93.25) R170.1@509.5,-57.02
NetLD7_1: LD7.1 R175.1 | length 69.8
  Top Layer w20: LD7.1@3946.26,5682.7 3945.98,5682.98 3945.98,5724.61 3958.23,5736.86 3958.23,5740.8 3960.04,5742.61 R175.1@3963.98,5742.61
NetQ1_1: Q1.1 R108.2 | length 51.5
  Bottom Layer w23: R108.2@1278.57,4052.06 1292.35,4038.28 Q1.1@1324.33,4038.28
NetQ2_1: Q2.1 R109.2 | length 51.5
  Bottom Layer w23: R109.2@1281.4,4558.48 1295.18,4544.7 Q2.1@1327.16,4544.7
NetQ3_1: Q3.1 R110.2 | length 51.5
  Bottom Layer w23: R110.2@1286,5031.08 1299.78,5017.3 Q3.1@1331.76,5017.3
NetQ4_1: Q4.1 R111.2 | length 51.5
  Bottom Layer w23: R111.2@1280,3496.08 1293.78,3482.3 Q4.1@1325.76,3482.3
NetR21_1: R21.1 U7.1 | length 129.4
  Top Layer w38: R21.1@787.6,4784.11 U7.1@787.6,4913.53
NetR22_1: R22.1 U8.1 | length 138.1
  Top Layer w38: R22.1@791.1,4230.61 791.1,4367.16 791.79,4367.84 U8.1@792.42,4367.84
NetR24_1: R24.1 U9.1 | length 126.1
  Top Layer w38: R24.1@792.1,3708.61 792.1,3833.16 792.79,3833.84 U9.1@793.42,3833.84
NetR26_1: R26.1 U10.5 | length 109.9
  Top Layer w9.5: 562.4,3343.08 562.4,3348.89 U10.5@572.82,3359.3
  Top Layer w20: R26.1@508.6,3295.61 508.6,3296.59 517.3,3305.29 550.69,3305.29 562.4,3317.01 562.4,3343.08
NetR28_1: R28.1 R30.2 U10.8 | length 147
  Top Layer w9: U10.8@690.12,3398.7 721,3398.7 v1@726,3403.7 ; v1@734,3402.7 738.5,3402.7 R28.1@769.5,3371.7
  Bottom Layer w9: v1(724,3402.7) 738,3402.7 R30.2@771,3369.7
NetR35_2: R35.2 R36.1 U2.2 | length 117
  Top Layer w6: R35.2@3554.28,4396.32 ccw(c3554.28,4413.09) 3571.04,4413.09 U2.2@3571.04,4452.8
  Top Layer w8: R36.1@3551.22,4346.61 3554.28,4349.66 R35.2@3554.28,4396.32
NetR37_2: R37.2 R38.1 U3.2 | length 112.8
  Top Layer w6: 4169.71,4189.46 4169.61,4189.55 4169.61,4224.8 U3.2@4169.71,4224.89
  Top Layer w8: R38.1@4164.22,4113.61 R37.2@4164.22,4156.61 ccw(c4150.97,4169.86) 4169.71,4169.86 4169.71,4189.46
NetR78_2: R78.2 XTAL1.1 | length 89.5
  Bottom Layer w10: XTAL1.1@4068.68,1356.8 4095.68,1383.8 R78.2@4146.98,1383.8
NetR79_1: R79.1 S3.1 | length 244
  Top Layer w20: S3.1@181.41,580.65 v1(355.45,580.65)
  Bottom Layer w20: v1(355.45,580.65) R79.1@355.45,650.61
NetR92_1: R92.1 R94.2 U7.5 | length 204.4
  Top Layer w20: v1(770.6,5252.61) 770.6,5191.24 780.28,5181.56 U7.5@788.42,5181.56
  Bottom Layer w20: v1(770.6,5252.61) 819.91,5252.61 R94.2@822,5254.7 ; R94.2@818,5251.7 819,5252.7 R92.1@886.5,5252.7
NetR93_1: R93.1 R95.2 U6.7 | length 529.2
  Top Layer w10: v1(566.65,5853.8) v1(566.65,5853.8) 596.87,5853.76 U6.7@596.91,5853.72
  Top Layer w20: v1(850.6,5646.61) R93.1@900.1,5646.61
  SIG1 w20: v1(566.65,5853.8) 694.87,5853.8 850.6,5698.08 v1(850.6,5646.61)
  Bottom Layer w20: v1(850.6,5646.61) R95.2@900.1,5646.61
NetR96_1: R96.1 R98.2 U8.5 | length 236.6
  Top Layer w20: v1(749.02,4709.7) 749.02,4645.24 758.7,4635.56 U8.5@792.42,4635.56
  Bottom Layer w20: v1(749.02,4709.7) R98.2@801,4709.7 ; R98.2@801,4708.7 869.5,4708.7 R96.1@872.5,4705.7
NetR100_1: R100.1 R101.2 U9.5 | length 220.4
  Top Layer w20: v1(774.75,4170.7) 774.75,4111.24 784.44,4101.56 U9.5@793.42,4101.56
  Bottom Layer w20: v1@774.75,4168.7 776.75,4170.7 822.5,4170.7 R101.2@829,4164.2 ; R101.2@831,4162.7 R100.1@911.5,4162.7
NetR106_2: R106.2 U10.3 | length 200.7
  Top Layer w9: v1(530,3398.7) U10.3@579.88,3398.7
  Bottom Layer w9: v1(530,3398.7) 530,3458.7 573,3501.7 R106.2@603,3501.7
NetR107_2: R107.2 T1.24 | length 117.5
  Top Layer w20: R107.2@728.22,1737.61 834.78,1737.61 ccw(c834.78,1751.58) 841.66,1739.42 ccw(c834.78,1751.58) T1.24@844.66,1741.7
NetR114_2: R114.2 T1.21 | length 120.2
  Top Layer w20: R114.2@725,1893.61 ccw(c729.6,1898.21) 729.6,1891.7 T1.21@844.66,1891.7
NetR117_2: R117.2 T1.18 | length 119.7
  Top Layer w20: R117.2@725,2041.7 T1.18@844.66,2041.7
NetR123_2: R123.2 T1.15 | length 121.1
  Top Layer w20: R123.2@723.62,2192.09 ccw(c724.57,2193.04) 724.57,2191.7 T1.15@844.66,2191.7
NetU5_27: U5.27 VPP_TP1.1 | length 164.3
  Top Layer w10: U5.27@3848.77,1751.38 3848.77,1656.57 3885,1620.34 VPP_TP1.1@3885,1602.05
OC_N: R179.1 U14.10 U14.14 U14.18 U14.22 | length 325.8
  Top Layer w8: v1(4969,5623.7) 4969,5619.05 4985.33,5602.72 U14.10@5000.92,5602.72 ; v3(4972.6,5535.61) 4972.6,5533.78 4982.28,5524.09 5000.8,5524.09 U14.14@5000.92,5523.98 ; v1(5120.6,5425.61) 5120.6,5429.94 5124.6,5433.94 5124.6,5458.68 U14.22@5124.94,5459.02
  Top Layer w9: 5037.58,5433.32 5046.2,5441.94 U14.18@5046.2,5459.02 5045.77,5458.59 5045.77,5445.76
  Top Layer w15: v1@4938.67,5361.83 v1(4942.05,5365.2) 4972.88,5365.2 R179.1@4989,5381.32 4989,5412.7 5001,5424.7 5028.96,5424.7 5037.58,5433.32
  SIG1 w8: v3(4972.6,5535.61) 4996,5535.61
P1.0: R69.2 U4.21 | length 287
  Top Layer w10: v4(3916.54,5115.47) 3948.54,5083.47 U4.21@4001.71,5083.47
  Bottom Layer w10: R69.2@3747.04,5161.57 3870.44,5161.57 v4(3916.54,5115.47)
P1.1: R70.2 U4.22 | length 282
  Top Layer w10: v4(3885,5076.7) 3897.91,5063.79 U4.22@4001.71,5063.79
  Bottom Layer w10: R70.2@3747.04,5129.86 3831.84,5129.86 v4(3885,5076.7)
P1.2: R71.2 U4.23 | length 261.5
  Top Layer w10: v4(3861,5047.7) 3864.6,5044.1 U4.23@4001.71,5044.1
  Bottom Layer w10: R71.2@3747.09,5060.61 3844.85,5060.61 3857.75,5047.7 v4(3861,5047.7)
P1.3: R72.2 U4.24 | length 256.9
  Top Layer w10: v4(3832.68,5025.52) 3834.38,5023.83 4002.24,5023.83 U4.24@4002.52,5024.11
  Bottom Layer w10: R72.2@3747.09,5027.14 3747.9,5026.33 3831.87,5026.33 v4(3832.68,5025.52)
P1.7: U4.28
P2.0: R39.2 U4.29 | length 557.2
  Top Layer w10: R39.2@3548.22,5114.61 3548.22,5070.98 3693.21,4925.99 U4.29@4001.71,4925.99
P2.1: R42.2 U4.30 | length 500
  Top Layer w10: R42.2@3548.22,5018.61 3552.16,5018.61 3664.46,4906.31 U4.30@4001.71,4906.31
P2.2: R43.2 U4.31 | length 465.5
  Top Layer w10: R43.2@3548.22,4915.61 3552.16,4915.61 3581.14,4886.62 U4.31@4001.71,4886.62
P2.3: R44.2 U4.32 | length 474.3
  Top Layer w10: R44.2@3548.22,4816.61 3552.16,4816.61 3602.49,4866.94 U4.32@4001.71,4866.94
P2.4: R45.2 U4.33 | length 505.9
  Top Layer w10: R45.2@3548.22,4720.61 3552.16,4720.61 3678.8,4847.25 U4.33@4001.71,4847.25
P2.5: R46.2 U4.34 | length 538.8
  Top Layer w10: R46.2@3548.22,4621.61 3552.16,4621.61 3758.12,4827.57 U4.34@4001.71,4827.57
PWDN_LVL: R47.1 R55.2 U2.3 | length 142.7
  Top Layer w6: U2.3@3584.82,4452.8 3584.82,4431.76 ccw(c3598.6,4431.76) v1(3598.6,4417.98)
  Top Layer w8: v1(3598.6,4417.98) cw(c3567.58,4386.96) 3611.45,4386.96 R47.1@3611.45,4370.42
  Bottom Layer w8: v1(3598.6,4417.98) cw(c3567.58,4386.96) 3611.45,4386.96 R55.2@3611.45,4372.39
PWDN_MSP: U2.6 U4.37 | length 581.7
  Top Layer w6: U2.6@3584.82,4488.23 3584.82,4500.36 3584.72,4521.54 cw(c3651.71,4521.61) 3584.73,4521.97 3584.82,4538.94
  Top Layer w8: 3584.82,4538.94 3584.82,4565.48 cw(c3666.61,4565.48) 3608.78,4623.32 cw(c3679.49,4552.61) 3679.49,4652.61 3774.18,4652.61 ccw(c3774.18,4752.61) 3844.89,4681.9 3902.21,4739.22 cw(c3972.93,4668.51) 3972.93,4768.51 U4.37@4001.71,4768.51
RESET_LVL: R51.1 R57.2 U2.4 | length 178.3
  Top Layer w6: U2.4@3598.6,4452.8 3620.64,4452.8 cw(c3620.64,4414.61) v1(3658.83,4414.61)
  Top Layer w8: v1(3658.83,4414.61) cw(c3647.21,4402.99) 3663.64,4402.99 R51.1@3663.64,4371.42
  Bottom Layer w8: R57.2@3658.83,4376.61 R57.2@3663.64,4371.8 ; v1(3658.83,4414.61) cw(c3647.21,4402.99) 3663.64,4402.99 R57.2@3663.64,4371.8 ; R57.2@3663.64,4371.8 3663.82,4371.61 R57.2@3663.64,4371.42 R57.2@3663.64,4371.8
RESET_MSP: U2.5 U4.38 | length 554.4
  Top Layer w6: U2.5@3598.6,4488.23 3600.4,4565.48
  Top Layer w8: 3600.69,4565.48 cw(c3651.92,4565.48) 3615.7,4601.71 3616.6,4602.61 cw(c3657.64,4561.56) 3657.64,4619.61 3780.18,4619.61 ccw(c3780.18,4719.61) 3850.89,4648.9 3928.6,4726.61 cw(c3982.24,4672.96) 3982.24,4748.83 U4.38@4001.71,4748.83
RESET_N: C46.1 J8.2 J10.2 R34.1 R39.1 R57.1 R80.2 S3.2 U5.59 | length 9403.8
  Top Layer w8: S3.2@181.41,836.56 411.16,836.56 J10.2@485.95,761.76 ; J8.2@3289.6,5166.61 3117.93,4993.87 cw(c3101,5010.7) 3117.83,4993.77 2928.84,4805.85 ccw(c2983.27,4751) 2928.63,4805.64 ccw(c2983.27,4751) 2906,4751 2906,3501.42 ccw(c3006,3501.42) 2935.29,3430.71 3366.71,2999.29 cw(c3296,2928.58) 3396,2928.58 3396,2818.63 ccw(c3496,2818.63) 3425.23,2747.98 ccw(c3496,2818.63) 3425.29,2747.92 v3(3637.6,2535.61) 3649.74,2535.61 cw(c3649.74,2435.61) 3749.74,2435.61 3749.74,2406.42 3749.14,2385.38 ccw(c3773,2384.7) 3749.14,2383.83 3749.48,2374.45 3750.35,2350.7 U5.59@3750.35,2255.08
  Top Layer w10: J8.2@3289.6,5166.61 3341.6,5114.61 R39.1@3500.98,5114.61 v1(3500.98,5070.98)
  Bottom Layer w8: R80.2@187.29,822.42 329.26,822.42 354.5,797.19 C46.1@354.5,793.25 ; C46.1@354.5,789.85 445.87,789.85 477.36,758.36 715.99,996.99 cw(c786.7,926.28) 786.7,1026.28 1970.52,1026.28 ccw(c1970.52,1126.28) 2041.24,1055.57 2783.36,1797.7 ccw(c2712.65,1868.41) 2812.65,1868.41 2812.65,1995.03 cw(c2912.65,1995.03) 2841.94,2065.74 3283.58,2507.38 cw(c3354.29,2436.67) 3354.29,2536.67 3642.51,2536.67 cw(c3642.51,2436.67) 3713.22,2507.38 3794.44,2426.17 R34.1@3798.37,2426.17 R34.1@3797.37,2427.17
  Bottom Layer w10: v1(3500.98,5070.98) ccw(c3580.06,5070.98) 3524.14,5015.07 3667.31,4871.9 cw(c3596.6,4801.18) 3696.6,4801.18 3696.6,4340.61 cw(c3680.17,4340.61) 3680.17,4324.17 R57.1@3663.64,4324.17
RESETN_1: J1.60 J2.5 | length 701.2
  Top Layer w10: J2.5@7833.6,334.61 8220.5,334.61 v1(8379.21,493.31)
  Bottom Layer w10: v1(8379.21,493.31) J1.60@8469.11,493.31
RESETN_2: J22.60
RESETN_CS: J4.60 R34.2 | length 3201.8
  Bottom Layer w10: R34.2@3845.62,2426.17 cw(c3880.48,2391.31) 3880.48,2440.61 4036.18,2440.61 cw(c4036.18,2340.61) 4106.89,2411.32 4502.46,2015.75 ccw(c4536.6,2049.89) 4536.6,2001.61 ccw(c4536.6,2069.2) 4584.4,2021.41 4661.31,2098.32 cw(c4732.02,2027.61) 4732.02,2127.61 5015.18,2127.61 ccw(c5015.18,2227.61) 5085.89,2156.9 5332.31,2403.32 cw(c5403.02,2332.61) 5403.02,2432.61 5937.18,2432.61 cw(c5937.18,2332.61) 6007.89,2403.32 6106.12,2305.08 cw(c6035.41,2234.37) 6135.41,2234.37 6135.41,2003.96 ccw(c6235.41,2003.96) 6164.7,1933.25 6191.97,1905.98 ccw(c6262.68,1976.69) 6262.68,1876.69 J4.60@6308.86,1876.69
RESETN_LP: J19.60
RJ45_ERTH: C82.2 C108.2 C109.2 J27.9 J27.10 J27.11 J27.12 M8.1 R145.1 R146.1 | length 185.9
  Top Layer w22: v1(473,1695.64) 473.38,1696.02 484.67,1696.02 517.91,1729.26 C82.2@517.91,1729.61 517.91,1729.95 484.64,1763.22 474.98,1763.22 v1(474.6,1763.61)
  Bottom Layer w22: R145.1@481.17,1531.62 481.17,1566.95 ; 482,2426.64 R146.1@482,2460.38
  other v1: 424,1638.64 331,1640.64 249,1641.64 65,1647.64 -142,1649.64 -28,1649.64 380,1697.64 298,1698.64 -134,1738 220,1766 119.33,1776 -135,1829 -75,1899.64 289,1914.6 494.7,1915.4 410.98,1916.47 -9,1931.64 -143,1957.64 -78,2005.64 -12,2037.64 -141,2054.64 -76,2102.64 -10,2134.64 461,2136 -140,2136.64 -75,2184.64 -149,2231 230.92,2241.27 366,2301.64 273,2303.64 -117,2323 493,2342.64 415,2358.64 322,2360.64 240,2361.64 24,2426 289,2430.64 -112.1,2431.49 207,2431.64 110,2433.64
RST/SBWTDIO: C25.1 J9.3 R10.2 R75.2 S2.2 U4.76 | length 2498.8
  Top Layer w10: U4.76@4531.24,5004.73 4575.23,5004.73 4587.35,4992.61 v4(4590.6,4992.61) ; S2.2@5215.05,4275.7 5217.02,4275.7 5276.3,4334.98 v4(5323,4334.98)
  SIG1 w10: v4(4590.6,4992.61) 4566.41,4968.42 4566.41,4917.72 4581.39,4902.73 4856.06,4902.73 4882.03,4928.7 5189,4928.7 5207,4910.7 5425.69,4910.7 5440.72,4925.72 5543.15,4925.72 5555.18,4913.7 5686,4913.7 v4(5704,4931.7) 5785.5,4931.7 J9.3@5827.6,4889.61 5826.89,4888.9 5826.89,4838.88 v4(5323,4334.98)
  Bottom Layer w10: C25.1@5319.38,4247.61 R75.2@5319.38,4295.61 5323,4299.23 v4(5323,4334.98) ; R10.2@5661.62,4932.7 5703,4932.7 v4(5704,4931.7)
RX_CLK: J32.1 R18.1 U5.42 | length 2162.6
  Top Layer w8: U5.42@4052.23,2033.57 4259.41,2033.57 cw(c4259.41,1998.04) 4284.52,2023.18 ; 4284.53,2023.17 4367.29,1940.41 ccw(c4438,2011.13) 4438,1911.13 4653.96,1911.13 cw(c4653.96,1811.13) 4724.67,1881.84 5513.71,1092.79 ccw(c5584.42,1163.5) 5584.42,1063.5 5604.07,1063.5 cw(c5604.07,963.5) 5674.78,1034.21 J32.1@5718.99,990 R18.1@5801.34,990
RX_CLK_1: J1.30 J2.27 | length 887.2
  Top Layer w10: J2.27@7833.6,1434.61 7910.6,1434.61 8145.6,1199.61 v1(8145.6,1101.61)
  Bottom Layer w10: v1(8145.6,1101.61) 8281.6,965.61 8468.97,965.61 J1.30@8469.11,965.75
RX_CLK_2: J22.30 R201.1 | length 528.9
  Bottom Layer w10: J22.30@6550.68,933.86 6774.35,933.86 6828.87,879.33 R201.1@7056.98,879.33
RX_CLK_LP: J19.30 R202.2 | length 288.8
  Bottom Layer w10: R202.2@7104.22,976.42 7167.72,976.42 7178.49,965.66 J19.30@7388.6,965.66
RX_CTRL: J31.1 R19.1 U5.49 | length 2264.7
  Top Layer w8: U5.49@3947.2,2255.08 3947.2,2290.6 cw(c4013.1,2290.6) 3966.5,2337.2 ; 3966.53,2337.23 cw(c4023.08,2280.62) 4023.08,2360.64 4568.9,2360.64 ccw(c4568.9,2460.64) 4639.61,2389.93 4739.77,2490.08 cw(c4788.98,2440.87) 4788.98,2510.46 5239.07,2510.46 cw(c5239.07,2363.54) 5386,2363.54 5386,2283.55 ccw(c5544.05,2283.55) 5544.05,2125.51 5600.88,2125.51 cw(c5600.88,2025.51) 5671.6,2096.22 J31.1@5718.99,2048.82 R19.1@5801.34,2048.82
RX_CTRL_1: J1.32 J2.7 | length 922.7
  Top Layer w10: J2.7@7833.6,434.61 8017.6,434.61 8379.08,796.09 v1(8379.08,933.09)
  Bottom Layer w10: v1(8379.08,933.09) 8380.24,934.25 J1.32@8469.11,934.25
RX_CTRL_2: J22.32 R130.1 | length 834.2
  Top Layer w10: v1(6735.6,638.61) v1(6735.6,965.61)
  Bottom Layer w10: J22.32@6550.68,965.35 6550.81,965.48 6735.47,965.48 v1(6735.6,965.61) ; v1(6735.6,638.61) 7054.98,638.61 R130.1@7056.98,636.61
RX_CTRL_LP: J19.32 R207.2 | length 287
  Bottom Layer w10: R207.2@7104.22,927.88 7109.95,933.61 7388.04,933.61 J19.32@7388.6,934.17
RX_D0: R17.1 R152.1 R154.2 U5.44 | length 2307.9
  Top Layer w8: U5.44@4051.41,2072.12 4731.45,2072.12 cw(c4731.45,1972.12) 4802.16,2042.84 4833.5,2011.5 4836.33,2008.67 ccw(c4849.76,2022.11) 4863.2,2008.67 4863.98,2009.45 cw(c4877.42,1996.02) 4890.85,2009.45 cw(c4877.42,1996.02) 4890.85,1982.58 4875.13,1966.86 ccw(c4888.56,1953.42) 4875.13,1939.99 ccw(c4888.56,1953.42) 4902,1939.99 4917.72,1955.71 cw(c4931.16,1942.28) 4944.59,1955.71 cw(c4931.16,1942.28) 4944.59,1928.84 4943.81,1928.06 ccw(c4957.24,1914.63) 4943.81,1901.19 4968.74,1876.26 5498.71,1346.29 ccw(c5627.95,1475.53) 5627.95,1292.76 cw(c5627.95,1225.61) 5695.1,1225.61 R152.1@5695.1,1205.42 5751.99,1205.42 5796.12,1205.42 cw(c5796.12,1201.38) R17.1@5798.98,1204.24
  Bottom Layer w8: R154.2@5695.1,1205.42 5695.69,1204.83 5751.4,1204.83 v1(5751.99,1204.24)
RX_D0_1: J1.26 J2.23 | length 721
  Top Layer w10: J2.23@7833.6,1234.61 v1(8055.79,1234.61)
  Bottom Layer w10: v1(8055.79,1234.61) 8261.79,1028.61 8430.69,1028.61 8430.83,1028.46 8468.83,1028.46 J1.26@8469.11,1028.74
RX_D0_2: J22.26 R132.1 | length 690.3
  Top Layer w10: v1(6780.6,685.88) v1(6780.6,868.61)
  Bottom Layer w10: J22.26@6550.68,870.87 6552.94,868.61 v1(6780.6,868.61) ; v1(6780.6,685.88) 7056.25,685.88 R132.1@7056.98,685.15
RX_D0_LP: J19.26 R206.2 | length 285.9
  Bottom Layer w10: R206.2@7104.22,1024.97 7107.9,1028.65 J19.26@7388.6,1028.65
RX_D1: R16.1 R155.1 R158.2 U5.45 | length 2402.1
  Top Layer w8: U5.45@4051.41,2091.81 4455.62,2091.81 ccw(c4455.62,2120.99) 4484.8,2120.99 4484.8,2128.28 cw(c4510.59,2128.28) 4510.59,2154.08 cw(c4510.59,2127.67) 4537,2127.67 4537,2110.43 ccw(c4555.62,2110.43) 4555.62,2091.81 4810.88,2091.81 cw(c4810.88,1991.81) 4881.59,2062.52 5023.43,1920.68 5026.26,1917.85 ccw(c5039.69,1931.29) 5053.13,1917.85 5071.59,1936.32 cw(c5085.03,1922.89) 5098.46,1936.32 cw(c5085.03,1922.89) 5098.46,1909.45 5055.09,1866.08 ccw(c5068.52,1852.64) 5055.09,1839.21 ccw(c5068.52,1852.64) 5081.96,1839.21 5125.33,1882.58 cw(c5138.77,1869.15) 5152.2,1882.58 cw(c5138.77,1869.15) 5152.2,1855.71 5133.74,1837.24 ccw(c5147.17,1823.81) 5133.74,1810.37 5177.86,1766.25 5416.77,1527.34 ccw(c5487.48,1598.05) 5487.48,1498.05 5577.38,1498.05 cw(c5577.38,1398.05) 5648.09,1468.76 R155.1@5695.63,1421.22 v1(5739.6,1421.22) R16.1@5801.34,1421.22
  Bottom Layer w8: R158.2@5695.63,1421.22 v1(5739.6,1421.22)
RX_D1_1: J1.24 J2.19 | length 656.5
  Top Layer w10: J2.19@7833.6,1034.61 7842.6,1025.61 8233.6,1025.61 v1(8268.6,1060.61)
  Bottom Layer w10: v1(8268.6,1060.61) 8462.55,1060.61 8465.65,1063.7 J1.24@8469.11,1060.24
RX_D1_2: J22.24 R134.1 | length 608.7
  Top Layer w10: v1(6836.6,838.61) 6839.1,836.11 6839.1,736.11 v1(6841.6,733.61)
  Bottom Layer w10: J22.24@6550.68,839.37 6551.44,838.61 v1(6836.6,838.61) ; v1(6841.6,733.61) 6841.69,733.7 R134.1@7056.98,733.7
RX_D1_LP: J19.24 R205.2 | length 289.9
  Bottom Layer w10: R205.2@7104.22,1073.51 7166.69,1073.51 7180.06,1060.15 J19.24@7388.6,1060.15
RX_D2: J29.1 R15.1 U5.46 | length 2307
  Top Layer w8: U5.46@4051.41,2111.49 4340.25,2111.49 ccw(c4340.25,2171.97) 4383.01,2129.21 4414.22,2160.41 cw(c4484.93,2089.7) 4484.93,2189.7 4568.6,2189.7 4610.6,2189.7 cw(c4610.6,2170.7) 4629.6,2170.7 4629.6,2151.33 ccw(c4648.6,2151.33) 4667.6,2151.33 4667.6,2187.23 cw(c4686.6,2187.23) 4705.6,2187.23 4705.6,2151.33 ccw(c4724.6,2151.33) 4743.6,2151.33 4743.6,2187.23 cw(c4762.6,2187.23) 4781.6,2187.23 4781.6,2151.33 ccw(c4800.6,2151.33) 4819.6,2151.33 4819.6,2170.7 cw(c4838.6,2170.7) 4838.6,2189.7 4878.79,2189.7 4995.91,2189.7 cw(c4995.91,2089.7) 5066.62,2160.41 5484.22,1742.81 ccw(c5554.93,1813.52) 5554.93,1713.52 5607.14,1713.52 5607.19,1713.52 cw(c5607.19,1639.62) 5659.39,1691.94 5659.46,1691.87 J29.1@5718.99,1632.34 R15.1@5801.34,1632.34
RX_D2_1: J1.22 J2.15 | length 759.1
  Top Layer w10: J2.15@7833.6,834.61 8095.6,834.61 8309.47,1048.48 v1(8309.47,1085.48)
  Bottom Layer w10: v1(8309.47,1085.48) 8313.26,1085.48 8320.39,1092.61 J1.22@8464.17,1092.61
RX_D2_2: J22.22 R135.1 | length 516.9
  Bottom Layer w10: J22.22@6550.68,807.87 7027.41,807.87 7053.04,782.24 R135.1@7056.98,782.24
RX_D2_LP: J19.22 R204.2 | length 297
  Bottom Layer w10: R204.2@7104.22,1122.06 7160.15,1122.06 7190.56,1091.65 J19.22@7388.6,1091.65
RX_D3: J30.1 R14.1 U5.47 | length 2271.1
  Top Layer w8: U5.47@4051.41,2131.18 4255.37,2131.18 ccw(c4255.37,2231.18) 4326.08,2160.47 4370.62,2205.01 cw(c4441.33,2134.3) 4441.33,2234.3 4628.92,2234.3 4632.92,2234.3 ccw(c4632.92,2253.3) 4651.92,2253.3 4651.92,2266.87 cw(c4670.92,2266.87) 4689.92,2266.87 4689.92,2244.16 ccw(c4708.92,2244.16) 4727.92,2244.16 4727.92,2266.87 cw(c4746.92,2266.87) 4765.92,2266.87 4765.92,2244.16 ccw(c4784.92,2244.16) 4803.92,2244.16 4803.92,2266.87 cw(c4822.92,2266.87) 4841.92,2266.87 4841.92,2244.16 ccw(c4860.92,2244.16) 4879.92,2244.16 4879.92,2266.87 cw(c4898.92,2266.87) 4917.92,2266.87 4917.92,2253.3 ccw(c4936.92,2253.3) 4936.92,2234.3 4974.63,2234.3 5068.98,2234.3 cw(c5068.98,2134.3) 5139.69,2205.01 5390.71,1953.99 ccw(c5461.42,2024.7) 5461.42,1924.7 5593.45,1924.7 cw(c5593.45,1824.7) 5664.16,1895.41 J30.1@5718.99,1840.58 R14.1@5801.34,1840.58
RX_D3_1: J1.20 J2.11 | length 1016.3
  Top Layer w10: J2.11@7833.6,634.61 8159.6,634.61 8341.6,816.61 v1(8341.6,1120.67)
  Bottom Layer w10: v1(8341.6,1120.67) 8465.79,1120.67 8468.73,1123.61 J1.20@8469.11,1123.23
RX_D3_2: J22.20 R136.1 | length 567.4
  Top Layer w10: v1(6911.6,773.61) v1(6911.6,832.75)
  Bottom Layer w10: J22.20@6550.68,776.38 6908.83,776.38 v1(6911.6,773.61) ; v1(6911.6,832.75) 6912.58,831.77 7056,831.77 R136.1@7056.98,830.79
RX_D3_LP: J19.20 R203.2 | length 304
  Bottom Layer w10: R203.2@7104.22,1170.61 7152.6,1170.61 7200.06,1123.14 J19.20@7388.6,1123.14
RX_ER: J5.1 R13.1 U5.43 | length 2582.9
  Top Layer w8: U5.43@4051.41,2052.44 4409.93,2052.45 cw(c4409.93,1952.45) 4480.64,2023.16 4537.4,1966.4 ; 4537.43,1966.37 ccw(c4587.6,2016.59) 4587.6,1945.61 v3(4622.6,1945.61)
  Bottom Layer w8: v3(4622.6,1945.61) 4622.6,1906.03 cw(c4522.6,1906.03) 4593.31,1835.32 4571.6,1813.61 ccw(c4640.03,1745.17) 4543.25,1745.17 4543.25,1583.72 4543.25,1583.67 ccw(c4665.09,1583.66) 4578.94,1497.51 4578.99,1497.46 5138.47,937.98 ccw(c5209.18,1008.69) 5209.18,908.69 5611.56,908.69 cw(c5611.56,808.69) 5682.27,879.4 5723.06,838.61 R13.1@5807.35,838.61
RX_ER_1: J1.16 J2.35 | length 955.6
  Top Layer w10: J2.35@7833.6,1834.61 8394,1274.2 v1(8394,1186.22)
  Bottom Layer w10: v1(8394,1186.22) J1.16@8469.11,1186.22
RX_ER_2: J22.16
RX_ER_CS: J4.16 R13.2 | length 692.7
  Bottom Layer w8: R13.2@5854.6,838.61 5982.89,838.61 ccw(c5982.89,938.61) 6053.6,867.9 6096.36,910.66 ccw(c6025.65,981.37) 6125.65,981.37 6125.65,1089.5 cw(c6225.65,1089.5) 6154.94,1160.21 cw(c6211.84,1103.32) 6211.84,1183.78 J4.16@6308.86,1183.78
RX_ER_LP: J19.16
RXCLK_CS: J4.30 R18.2 | length 1002.2
  Top Layer w8: R18.2@5848.59,990 cw(c5903.22,990) 5864.59,1028.63 cw(c5892.03,1001.19) 5892.03,1040 5972.81,1040 cw(c5972.81,1025) 5983.42,1035.61 5986.75,1032.27 cw(c5966.1,1011.62) 5995.31,1011.62 ccw(c6024.97,1011.62) 6024.97,981.95 6110.66,981.95 ccw(c6110.66,1007.24) 6135.95,1007.24 ccw(c6112.59,1007.24) 6130.5,1022.24 ccw(c6112.59,1007.24) 6112.59,1030.61 v3(6064.14,1030.61)
  Bottom Layer w8: v3(6064.14,1030.61) 6064.14,1263.17 cw(c6164.14,1263.17) 6093.43,1333.88 6134.51,1374.96 cw(c6205.22,1304.25) 6205.22,1404.25 J4.30@6308.86,1404.25
RXCTRL_CS: J4.32 R19.2 | length 1011.8
  Top Layer w8: R19.2@5848.59,2048.82 5892.8,2093.03 cw(c5916.72,2069.11) 5916.72,2102.94 6005.42,2102.94 cw(c6005.42,2022.35) 6062.37,2079.38 cw(c6005.42,2022.35) 6062.41,2079.34 6193.72,1948.03 cw(c6123.01,1877.32) 6223.01,1877.32 6223.01,1504.78 ccw(c6320.63,1504.78) v3(6251.6,1435.75)
  Bottom Layer w8: v3(6251.6,1435.75) J4.32@6308.86,1435.75
RXD0_CS: J4.26 R17.2 | length 1026
  Top Layer w8: R17.2@5848.59,1204.24 5848.59,1229.1 cw(c5897.23,1229.1) 5897.23,1277.75 5948.75,1277.75 cw(c5948.75,1232.43) 5994.06,1232.43 5994.06,1178.06 cw(c5968.6,1178.06) 5968.6,1152.61 5906.8,1152.61 ccw(c5906.8,1138.61) 5892.8,1138.61 5892.8,1123.1 ccw(c5908.6,1123.1) 5908.6,1107.3 6054.7,1107.3 ccw(c6054.7,1151.77) v3(6099.17,1151.77)
  Bottom Layer w8: v3(6099.17,1151.77) 6099.17,1267.63 cw(c6172.8,1267.63) 6124.78,1323.44 cw(c6172.8,1267.63) 6172.8,1341.26 J4.26@6308.86,1341.26
RXD1_CS: J4.24 R16.2 | length 918.4
  Top Layer w8: R16.2@5848.59,1421.22 5870.24,1399.57 ccw(c5933.34,1462.66) 5933.34,1373.43 5985.24,1373.43 ccw(c5985.24,1398.14) 6009.94,1398.14 6009.94,1422.27 cw(c6025.83,1422.27) 6025.83,1438.16 6038.78,1438.16 cw(c6038.78,1419.91) 6057.02,1419.91 6057.02,1366.28 cw(c6030.37,1366.28) 6030.37,1339.63 6015.57,1339.63 ccw(c6015.57,1318.7) 5994.64,1318.7 ccw(c6014.64,1318.7) 6014.64,1298.7 6038.18,1298.7 cw(c6038.18,1279.86) 6057.02,1279.86 6057.02,1222.19 ccw(c6087.62,1222.19) 6087.62,1191.59 6111.16,1191.59 ccw(c6111.16,1212.78) 6132.34,1212.78 6132.34,1264.49 cw(c6146.85,1264.49) v3(6146.85,1279)
  Bottom Layer w8: v3(6146.85,1279) 6156.02,1288.17 cw(c6208.15,1236.04) 6208.15,1309.76 J4.24@6308.86,1309.76
RXD2_CS: J4.22 R15.2 | length 970.7
  Top Layer w8: R15.2@5848.59,1632.34 5880.22,1600.7 ccw(c5916.12,1636.61) 5916.12,1585.83 5983.96,1585.83 ccw(c5983.96,1603) 6001.13,1603 6001.13,1633.68 cw(c6023.17,1633.68) 6023.17,1655.72 6090.28,1655.72 cw(c6090.28,1633.09) 6112.91,1633.09 6112.91,1345.53 ccw(c6130.53,1345.53) 6130.53,1327.92 6148.6,1327.92 cw(c6148.6,1305.17) 6164.68,1321.26 cw(c6135.27,1291.84) 6176.87,1291.84 v3(6176.87,1221.34)
  Bottom Layer w8: v3(6176.87,1221.34) cw(c6176.87,1223.61) 6174.6,1223.61 cw(c6229.26,1223.61) 6229.26,1278.27 J4.22@6308.86,1278.27
RXD3_CS: J4.20 R14.2 | length 1005.8
  Top Layer w8: R14.2@5848.59,1840.58 5879.95,1809.22 ccw(c5922.46,1851.73) 5922.46,1791.61 5987.52,1791.61 ccw(c5987.52,1813.96) 6009.87,1813.96 6009.87,1826.64 cw(c6027.23,1826.64) 6027.23,1844 6033.36,1844 cw(c6033.36,1823.74) 6053.62,1823.74 6053.62,1810.91 ccw(c6072.92,1810.91) 6072.92,1791.61 6091.18,1791.61 cw(c6091.18,1744.93) 6137.87,1744.93 6137.87,1724.41 ccw(c6187.34,1724.41) 6138.24,1718.38 ccw(c6187.34,1724.41) 6152.36,1689.43 ccw(c6216.75,1734.99) 6160.97,1679.21 ; 6160.99,1679.19 cw(c6132.9,1651.14) 6172.6,1651.14 6172.6,1386.09 ccw(c6220.4,1386.09) 6186.6,1352.29 6189.26,1349.63 cw(c6152.24,1312.61) 6204.6,1312.61 6204.6,1298.7 ccw(c6255.52,1298.7) 6219.51,1262.7 v3(6234.6,1247.61)
  Bottom Layer w8: v3(6234.6,1247.61) ccw(c6235.43,1247.61) 6235.43,1246.77 J4.20@6308.86,1246.77
SMI_DISABLE: J40.1 U5.50 | length 2012.7
  Top Layer w8: U5.50@3928.42,2256 3928.42,2319.7 cw(c3965.64,2319.7) 3939.32,2346.02 3965.62,2372.32 cw(c4036.33,2301.61) 4036.33,2401.61 4532.18,2401.61 ccw(c4532.18,2501.61) 4602.9,2430.9 4766.32,2594.32 cw(c4837.03,2523.61) 4837.03,2623.61 5575.38,2623.61 cw(c5575.38,2523.61) 5646.09,2594.32 J40.1@5718.99,2521.41
SUPPLYMODESEL: J37.1 U5.23 | length 2609
  Top Layer w8: U5.23@3770.03,1751.38 3770.03,1579.6 ccw(c3850.9,1579.6) 3793.72,1522.42 4800.48,515.65 ccw(c4871.19,586.36) 4871.19,486.36 5610.24,486.36 cw(c5610.24,386.36) 5680.95,457.07 J37.1@5718.99,419.03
